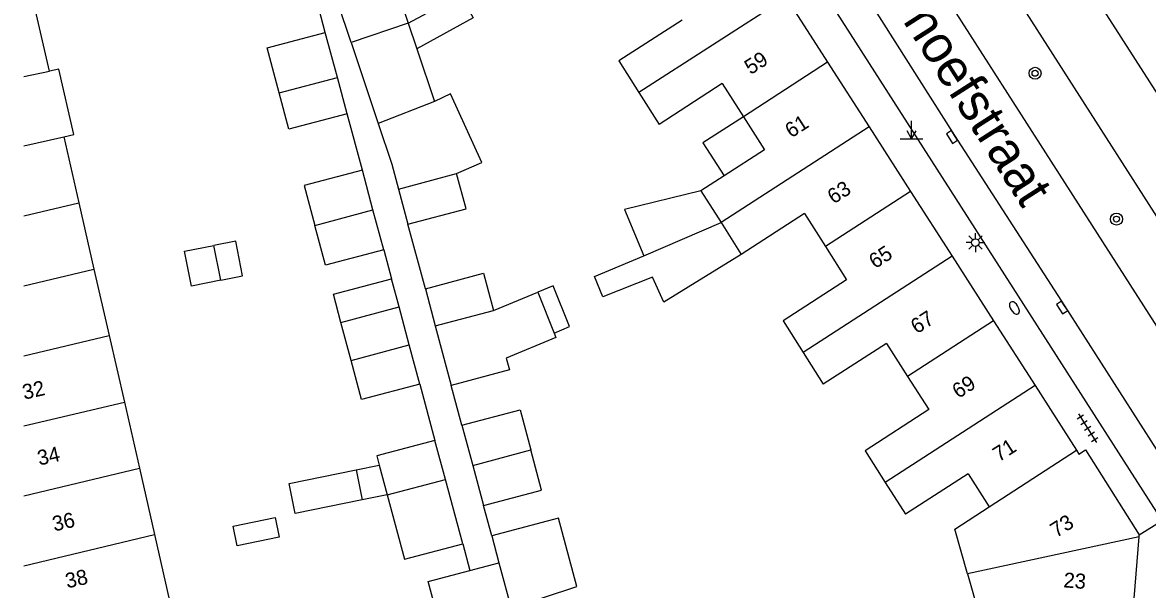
# Model space of a CAD drawing. Extents: x 132998 to 136004, y 396998 to 398512.
# Drawn here: x 132999.9 to 133074.7, y 397340.6 to 397378.3 of the extents above; entities that cross this region are included whole.
import ezdxf

# ---------------------------------------------------------------- set-up
doc = ezdxf.new("R2010")
doc.units = 0
for name, color, linetype in [('gg-afsc-erfafscheiding', 7, 'Continuous'), ('gg-anno-huisnummerreeks BGT', 7, 'Continuous'), ('gg-anno-openbare ruimte label', 7, 'Continuous'), ('gg-bbg-gedigitaliseerde bebouwing', 7, 'Continuous'), ('gg-bbg-gedigitaliseerde bijgebouw', 7, 'Continuous'), ('gg-bbg-hoofdgebouw', 7, 'Continuous'), ('gg-bbg-luifel en loopbrug', 7, 'Continuous'), ('gg-bbg-tussenscheiding', 7, 'Continuous'), ('gg-knt-verharding', 7, 'Continuous'), ('gg-knt-verharding nz', 7, 'Continuous'), ('gt-grn-weggrens', 7, 'Continuous'), ('gt-symb-boom', 7, 'Continuous'), ('gt-symb-brandkraan', 7, 'Continuous'), ('gt-symb-kolk', 7, 'Continuous'), ('gt-symb-lichtmast', 7, 'Continuous'), ('gt-symb-markant object', 7, 'Continuous'), ('gt-symb-tegel verharding', 7, 'Continuous')]:
    doc.layers.add(name, color=color, linetype=linetype)

# ---------------------------------------------------------------- blocks, each defined once
blk = doc.blocks.new('gt0-BR')
at = {"layer": 'gt-symb-brandkraan'}
for centre, radius, start, end in [((-0.244, 0), 0.206, 107.56694, 252.43307), ((0.599, -2.664), 3, 106.89205, 107.56694), ((0, -0.691), 0.938, 73.10799, 106.89205), ((-0.599, -2.664), 3, 72.43309, 73.10799), ((0.244, 0), 0.206, 287.56695, 72.43309), ((0.599, 2.664), 3, 252.43307, 253.10797), ((0, 0.691), 0.938, 253.10797, 286.89206), ((-0.599, 2.664), 3, 286.89206, 287.56695)]:
    blk.add_arc(centre, radius, start, end, dxfattribs=at)
blk = doc.blocks.new('gt0-KOLK')
at = {"layer": 'gt-symb-kolk'}
blk.add_lwpolyline([(0, 0), (0.375, 0), (0.375, 0.4), (-0.375, 0.4), (-0.375, 0), (0, 0)], dxfattribs=at)
blk = doc.blocks.new('gt0-LMAST')
at = {"layer": 'gt-symb-lichtmast'}
for p, q in [((-0.182, 0.173), (-0.447, 0.438)), ((-0.005, 0.246), (-0.005, 0.621)), ((0.172, 0.173), (0.437, 0.438)), ((-0.255, -0.004), (-0.63, -0.004)), ((-0.182, -0.181), (-0.447, -0.446)), ((-0.005, -0.254), (-0.005, -0.629)), ((0.437, -0.446), (0.172, -0.181)), ((0.245, -0.004), (0.62, -0.004))]:
    blk.add_line(p, q, dxfattribs=at)
blk.add_circle((-0.005, -0.004), 0.25, dxfattribs=at)
blk = doc.blocks.new('gt0-BOOM')
at = {"layer": 'gt-symb-boom'}
for radius in [0.4, 0.2]:
    blk.add_circle((0, 0), radius, dxfattribs=at)
blk = doc.blocks.new('gt0-TEG1')
at = {"layer": 'gt-symb-tegel verharding'}
for p, q in [((-1.125, 0), (1.125, 0)), ((-0.9, -0.25), (-0.9, 0.25)), ((-0.45, -0.25), (-0.45, 0.25)), ((0, -0.25), (0, 0.25)), ((0.45, -0.25), (0.45, 0.25)), ((0.9, -0.25), (0.9, 0.25))]:
    blk.add_line(p, q, dxfattribs=at)
blk = doc.blocks.new('gt0-MARKOB')
at = {"layer": 'gt-symb-markant object'}
for p, q in [((0, 0), (0, 1.2)), ((-0.75, 0), (0.75, 0)), ((0, 0), (-0.3, 0.52)), ((0, 0), (0.3, 0.52))]:
    blk.add_line(p, q, dxfattribs=at)

msp = doc.modelspace()

# ---------------------------------------------------------------- linework, layer by layer
at = {"layer": 'gg-afsc-erfafscheiding'}
for p, q in [((133020.052, 397377.644), (133019.643, 397379.171)), ((133022.516, 397368.467), (133021.506, 397372.221)), ((133026.705, 397360.58), (133025.544, 397364.892)), ((133023.937, 397363.168), (133024.455, 397361.247)), ((133026.335, 397354.236), (133027.341, 397350.495)), ((133029.141, 397351.503), (133028.428, 397354.154)), ((133031.117, 397344.15), (133030.573, 397346.166)), ((133029.188, 397343.608), (133029.666, 397341.829))]:
    msp.add_line(p, q, dxfattribs=at)
at = {"layer": 'gg-bbg-gedigitaliseerde bebouwing'}
for p, q in [((133001.703, 397375.061), (133000.493, 397380.384)), ((133043.779, 397378.465), (133039.574, 397375.746)), ((133039.574, 397375.746), (133040.909, 397373.632)), ((133040.909, 397373.632), (133042.244, 397371.518)), ((133046.449, 397374.238), (133042.244, 397371.518)), ((133046.449, 397374.238), (133047.853, 397372.034)), ((133002.667, 397370.693), (133003.666, 397366.308)), ((133046.566, 397368.091), (133045.034, 397367.1)), ((133045.034, 397367.1), (133046.369, 397364.986)), ((133003.666, 397366.308), (133004.672, 397361.892)), ((133051.908, 397365.591), (133047.704, 397362.872)), ((133051.908, 397365.591), (133053.313, 397363.388)), ((133046.369, 397364.986), (133047.704, 397362.872)), ((133053.313, 397363.388), (133054.717, 397361.186)), ((133004.672, 397361.892), (133005.677, 397357.477)), ((133054.717, 397361.186), (133050.494, 397358.454)), ((133050.494, 397358.454), (133051.829, 397356.34)), ((133005.677, 397357.477), (133006.691, 397353.028)), ((133057.368, 397356.945), (133053.164, 397354.226)), ((133057.368, 397356.945), (133058.772, 397354.741)), ((133051.829, 397356.34), (133053.164, 397354.226)), ((133058.772, 397354.741), (133060.177, 397352.539)), ((133006.691, 397353.028), (133007.689, 397348.645)), ((133007.689, 397348.645), (133008.695, 397344.229)), ((133062.792, 397348.276), (133058.625, 397345.58)), ((133062.792, 397348.276), (133064.195, 397346.074)), ((133057.29, 397347.694), (133058.625, 397345.58)), ((133061.912, 397344.597), (133064.195, 397346.074)), ((133062.766, 397341.612), (133061.912, 397344.597)), ((133008.695, 397344.229), (133009.701, 397339.813)), ((133062.766, 397341.612), (133063.665, 397338.468))]:
    msp.add_line(p, q, dxfattribs=at)
for points in [[(133002.667, 397370.693), (133003.336, 397370.845), (133002.343, 397375.204), (133001.703, 397375.061)], [(133047.853, 397372.034), (133049.257, 397369.832), (133046.566, 397368.091)], [(133060.177, 397352.539), (133055.955, 397349.807), (133057.29, 397347.694)]]:
    msp.add_lwpolyline(points, dxfattribs=at)
at = {"layer": 'gg-bbg-gedigitaliseerde bijgebouw'}
for p, q in [((133023.832, 397383.452), (133025.568, 397378.246)), ((133025.568, 397378.246), (133026.138, 397376.538)), ((133020.855, 397374.651), (133020.052, 397377.644)), ((133021.779, 397376.963), (133023.576, 397371.575)), ((133026.138, 397376.538), (133027.304, 397373.041)), ((133021.506, 397372.221), (133020.855, 397374.651)), ((133023.223, 397365.832), (133022.516, 397368.467)), ((133024.924, 397367.206), (133025.544, 397364.892)), ((133023.937, 397363.168), (133023.223, 397365.832)), ((133013.11, 397361.147), (133012.651, 397363.47)), ((133026.705, 397360.58), (133027.368, 397358.106)), ((133031.23, 397359.148), (133034.187, 397360.355)), ((133034.187, 397360.355), (133035.267, 397357.633)), ((133021.091, 397358.347), (133024.955, 397359.383)), ((133025.635, 397356.847), (133024.955, 397359.383)), ((133021.771, 397355.811), (133021.091, 397358.347)), ((133027.368, 397358.106), (133028.428, 397354.154)), ((133026.335, 397354.236), (133025.635, 397356.847)), ((133029.141, 397351.503), (133029.861, 397348.82)), ((133028.036, 397347.903), (133027.341, 397350.495)), ((133022.109, 397348.529), (133022.514, 397346.531)), ((133023.644, 397348.84), (133024.173, 397346.867)), ((133029.861, 397348.82), (133030.573, 397346.166)), ((133029.188, 397343.608), (133028.036, 397347.903)), ((133031.117, 397344.15), (133031.601, 397342.34)), ((133029.666, 397341.829), (133031.601, 397342.34))]:
    msp.add_line(p, q, dxfattribs=at)
for points in [[(133021.779, 397376.963), (133020.03, 397382.208), (133023.832, 397383.452)], [(133016.991, 397373.615), (133016.188, 397376.608), (133020.052, 397377.644)], [(133021.506, 397372.221), (133017.639, 397371.2), (133016.991, 397373.615)], [(133028.787, 397368.242), (133030.466, 397368.988), (133028.388, 397373.558), (133027.304, 397373.041)], [(133023.576, 397371.575), (133024.474, 397368.883), (133024.924, 397367.206)], [(133022.516, 397368.467), (133018.649, 397367.446), (133019.359, 397364.796)], [(133025.544, 397364.892), (133029.412, 397365.913), (133028.787, 397368.242)], [(133023.937, 397363.168), (133020.07, 397362.146), (133019.359, 397364.796)], [(133013.11, 397361.147), (133011.145, 397360.759), (133010.686, 397363.081), (133012.651, 397363.47)], [(133026.705, 397360.58), (133030.568, 397361.616), (133031.23, 397359.148)], [(133035.267, 397357.633), (133035.381, 397357.346), (133032.084, 397355.963), (133032.291, 397355.19), (133028.428, 397354.154)], [(133026.335, 397354.236), (133022.468, 397353.215), (133021.771, 397355.811)], [(133029.141, 397351.503), (133033.009, 397352.525), (133033.725, 397349.856)], [(133027.341, 397350.495), (133023.474, 397349.474), (133023.644, 397348.84)], [(133030.573, 397346.166), (133034.44, 397347.187), (133033.725, 397349.856)], [(133022.514, 397346.531), (133018.057, 397345.629), (133017.653, 397347.627), (133022.109, 397348.529)], [(133024.173, 397346.867), (133025.321, 397342.587), (133029.188, 397343.608)], [(133032.412, 397339.32), (133036.777, 397340.77), (133035.557, 397345.322), (133031.117, 397344.15)], [(133027.713, 397338.06), (133026.898, 397341.098), (133029.666, 397341.829)]]:
    msp.add_lwpolyline(points, dxfattribs=at)
at = {"layer": 'gg-bbg-hoofdgebouw'}
for p, q in [((133050.699, 397379.964), (133053.458, 397375.659)), ((133053.458, 397375.659), (133056.216, 397371.355)), ((133056.216, 397371.355), (133058.975, 397367.05)), ((133058.975, 397367.05), (133061.733, 397362.746)), ((133061.733, 397362.746), (133064.492, 397358.441)), ((133064.492, 397358.441), (133067.25, 397354.137)), ((133067.25, 397354.137), (133070.007, 397349.835)), ((133074.171, 397344.071), (133074.181, 397344.2))]:
    msp.add_line(p, q, dxfattribs=at)
for points in [[(133070.007, 397349.835), (133070.17, 397349.58), (133070.61, 397349.86), (133074.181, 397344.2)], [(133073.11, 397337.58), (133073.65, 397337.52), (133074.171, 397344.071)]]:
    msp.add_lwpolyline(points, dxfattribs=at)
at = {"layer": 'gg-bbg-luifel en loopbrug'}
for p, q in [((133041.232, 397362.768), (133046.369, 397364.986)), ((133024.955, 397359.383), (133024.455, 397361.247)), ((133022.109, 397348.529), (133023.644, 397348.84)), ((133024.173, 397346.867), (133022.514, 397346.531))]:
    msp.add_line(p, q, dxfattribs=at)
for points in [[(133025.568, 397378.246), (133029.042, 397380.143), (133029.879, 397378.611), (133026.138, 397376.538)], [(133047.853, 397372.034), (133045.162, 397370.294), (133046.566, 397368.091)], [(133045.034, 397367.1), (133039.954, 397365.86), (133041.232, 397362.768)], [(133013.11, 397361.147), (133014.558, 397361.434), (133014.099, 397363.756), (133012.651, 397363.47)], [(133047.704, 397362.872), (133042.563, 397359.681), (133041.811, 397361.346), (133038.515, 397360.037), (133037.956, 397361.409), (133041.232, 397362.768)], [(133021.091, 397358.347), (133020.588, 397360.226), (133024.455, 397361.247)], [(133035.267, 397357.633), (133036.29, 397358.063), (133035.214, 397360.774), (133034.187, 397360.355)], [(133016.988, 397344.05), (133014.193, 397343.484), (133013.928, 397344.793), (133016.723, 397345.359), (133016.988, 397344.05)]]:
    msp.add_lwpolyline(points, dxfattribs=at)
at = {"layer": 'gg-bbg-tussenscheiding'}
for p, q in [((133050.699, 397379.964), (133040.909, 397373.632)), ((133025.568, 397378.246), (133021.779, 397376.963)), ((133000, 397374.708), (133001.703, 397375.061)), ((133053.458, 397375.659), (133047.853, 397372.034)), ((133016.991, 397373.615), (133020.855, 397374.651)), ((133027.304, 397373.041), (133023.576, 397371.575)), ((133056.216, 397371.355), (133046.369, 397364.986)), ((133000, 397370.084), (133002.667, 397370.693)), ((133024.924, 397367.206), (133028.787, 397368.242)), ((133058.975, 397367.05), (133053.313, 397363.388)), ((133000, 397365.432), (133003.666, 397366.308)), ((133019.359, 397364.796), (133023.223, 397365.832)), ((133061.733, 397362.746), (133051.829, 397356.34)), ((133000, 397360.776), (133004.672, 397361.892)), ((133027.368, 397358.106), (133031.23, 397359.148)), ((133064.492, 397358.441), (133058.772, 397354.741)), ((133000, 397356.121), (133005.677, 397357.477)), ((133021.771, 397355.811), (133025.635, 397356.847)), ((133067.25, 397354.137), (133057.29, 397347.694)), ((133000, 397351.454), (133006.691, 397353.028)), ((133029.861, 397348.82), (133033.725, 397349.856)), ((133064.195, 397346.074), (133070.007, 397349.835)), ((133000, 397346.808), (133007.689, 397348.645)), ((133024.173, 397346.867), (133028.036, 397347.903)), ((133000, 397342.151), (133008.695, 397344.229)), ((133074.171, 397344.071), (133062.766, 397341.612)), ((133031.601, 397342.34), (133032.412, 397339.32))]:
    msp.add_line(p, q, dxfattribs=at)
at = {"layer": 'gg-knt-verharding'}
for points in [[(133086.63, 397346.907), (133082.637, 397353.986), (133054.967, 397397.254)], [(133051.68, 397395.065), (133078.253, 397353.519), (133084.079, 397345.261)], [(133075.712, 397345.156), (133047.045, 397389.968), (133048.931, 397391.181)]]:
    msp.add_lwpolyline(points, dxfattribs=at)
at = {"layer": 'gg-knt-verharding nz'}
for points in [[(133089.547, 397351.404), (133084.802, 397358.864), (133068.973, 397383.593), (133059.175, 397398.83)], [(133048.931, 397391.181), (133053.959, 397383.304), (133061.893, 397370.787), (133069.215, 397359.444), (133078.957, 397344.197)]]:
    msp.add_lwpolyline(points, dxfattribs=at)
at = {"layer": 'gt-grn-weggrens'}
msp.add_line((133074.181, 397344.2), (133075.712, 397345.156), dxfattribs=at)

# ---------------------------------------------------------------- block references
at = {"layer": 'gt-symb-boom'}
for p in [(133067.251, 397374.92), (133072.665, 397365.218)]:
    msp.add_blockref('gt0-BOOM', p, dxfattribs=at)
at = {"layer": 'gt-symb-brandkraan', "rotation": -58.40750843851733}
msp.add_blockref('gt0-BR', (133065.879, 397359.308), dxfattribs=at)
at = {"layer": 'gt-symb-kolk'}
for p, rotation in [((133061.893, 397370.787), 122.33937708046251), ((133069.215, 397359.444), 122.83164893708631)]:
    msp.add_blockref('gt0-KOLK', p, dxfattribs=dict(at, rotation=rotation))
at = {"layer": 'gt-symb-lichtmast'}
msp.add_blockref('gt0-LMAST', (133063.289, 397363.658), dxfattribs=at)
at = {"layer": 'gt-symb-markant object'}
msp.add_blockref('gt0-MARKOB', (133059.041, 397370.562), dxfattribs=at)
at = {"layer": 'gt-symb-tegel verharding', "rotation": -57.53320054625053}
msp.add_blockref('gt0-TEG1', (133070.741, 397351.303), dxfattribs=at)

# ---------------------------------------------------------------- texts
at = {"layer": 'gg-anno-huisnummerreeks BGT'}
for s, rotation, p in [('59', 32.7, (133048.337, 397374.797)), ('61', 32.7, (133051.037, 397370.583)), ('63', 32.7, (133053.854, 397366.188)), ('65', 32.7, (133056.611, 397361.884)), ('67', 32.7, (133059.392, 397357.546)), ('32', 12.8, (133000.034, 397353.198)), ('69', 32.7, (133062.148, 397353.244)), ('71', 32.7, (133064.848, 397349.031)), ('34', 12.8, (133001.032, 397348.813)), ('36', 12.8, (133002.028, 397344.432)), ('73', 32.3, (133068.664, 397343.991)), ('38', 12.8, (133002.89, 397340.642)), ('23', 355.5, (133069.113, 397340.719))]:
    msp.add_text(s, height=1, rotation=rotation, dxfattribs=at).set_placement(p)
at = {"layer": 'gg-anno-openbare ruimte label'}
msp.add_text('Waterhoefstraat', height=2.5, rotation=302.6, dxfattribs=at).set_placement((133053.619, 397385.923))

doc.saveas('drawing.dxf')
